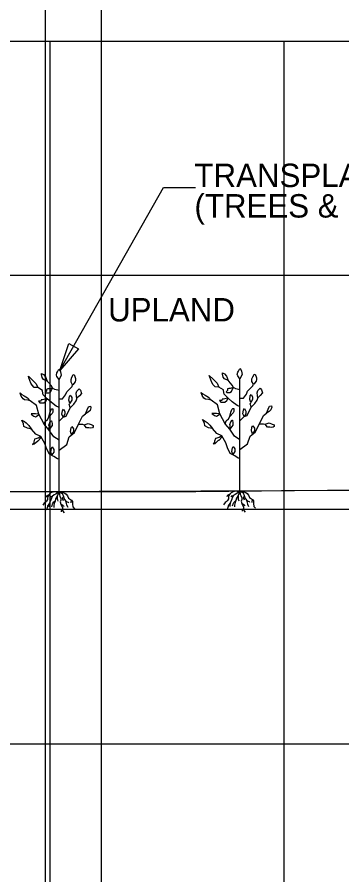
# Model space of a CAD drawing. Extents: x 1578769 to 1579225, y 724002 to 724828.
# Drawn here: x 1578839.43 to 1578846.37, y 724264.34 to 724282.66 of the extents above; entities that cross this region are included whole.
import ezdxf

# ---------------------------------------------------------------- set-up
doc = ezdxf.new("R2010")
doc.units = 0
for name, color, linetype in [('1', 7, 'Continuous'), ('Default', 7, 'Continuous'), ('Old_Level_1', 7, 'Continuous'), ('Old_Level_41', 7, 'Continuous'), ('R_Exist Surface', 7, 'Continuous')]:
    doc.layers.add(name, color=color, linetype=linetype)

msp = doc.modelspace()

# ---------------------------------------------------------------- linework, layer by layer
at = {"layer": '1'}
for p, q in [((1578840.327, 724272.523), (1578840.327, 724274.923)), ((1578844.196, 724272.536), (1578844.196, 724274.936)), ((1578840.332, 724272.518), (1578840.333, 724272.522)), ((1578844.201, 724272.531), (1578844.202, 724272.535))]:
    msp.add_line(p, q, dxfattribs=at)
for points in [[(1578840.345, 724275.111), (1578842.56, 724279.02), (1578843.246, 724279.02)], [(1578844.483, 724274.822), (1578844.452, 724274.879), (1578844.452, 724274.936), (1578844.47, 724274.98), (1578844.496, 724275.03), (1578844.521, 724275.037), (1578844.546, 724274.955), (1578844.546, 724274.917), (1578844.54, 724274.885), (1578844.489, 724274.822)], [(1578840.327, 724274.683), (1578840.239, 724274.708), (1578840.188, 724274.733), (1578840.163, 724274.784), (1578840.087, 724274.872), (1578840.075, 724274.885)], [(1578840.614, 724274.809), (1578840.583, 724274.866), (1578840.583, 724274.923), (1578840.602, 724274.967), (1578840.627, 724275.017), (1578840.652, 724275.024), (1578840.677, 724274.942), (1578840.677, 724274.904), (1578840.671, 724274.872), (1578840.62, 724274.809)], [(1578844.196, 724274.696), (1578844.108, 724274.721), (1578844.057, 724274.746), (1578844.032, 724274.797), (1578843.956, 724274.885), (1578843.944, 724274.898)], [(1578840.314, 724274.329), (1578840.264, 724274.354), (1578840.163, 724274.43), (1578840.075, 724274.506), (1578839.986, 724274.594), (1578839.974, 724274.67), (1578839.974, 724274.683), (1578839.873, 724274.746)], [(1578840.327, 724274.506), (1578840.403, 724274.506), (1578840.466, 724274.594), (1578840.491, 724274.657), (1578840.605, 724274.771), (1578840.617, 724274.809)], [(1578840.706, 724274.506), (1578840.693, 724274.626), (1578840.706, 724274.67), (1578840.756, 724274.721), (1578840.788, 724274.689), (1578840.807, 724274.62), (1578840.762, 724274.569), (1578840.706, 724274.519)], [(1578844.183, 724274.342), (1578844.133, 724274.367), (1578844.032, 724274.443), (1578843.944, 724274.519), (1578843.855, 724274.607), (1578843.843, 724274.683), (1578843.843, 724274.696), (1578843.742, 724274.759)], [(1578844.196, 724274.519), (1578844.272, 724274.519), (1578844.335, 724274.607), (1578844.36, 724274.67), (1578844.474, 724274.784), (1578844.486, 724274.822)], [(1578844.575, 724274.519), (1578844.562, 724274.639), (1578844.575, 724274.683), (1578844.625, 724274.733), (1578844.657, 724274.702), (1578844.676, 724274.632), (1578844.631, 724274.582), (1578844.575, 724274.531)], [(1578839.708, 724274.468), (1578839.664, 724274.481), (1578839.589, 724274.487), (1578839.557, 724274.506), (1578839.519, 724274.563), (1578839.494, 724274.626), (1578839.494, 724274.632), (1578839.532, 724274.601), (1578839.582, 724274.575), (1578839.652, 724274.531), (1578839.708, 724274.468)], [(1578840.327, 724274.038), (1578840.34, 724274.038), (1578840.415, 724274.114), (1578840.478, 724274.14), (1578840.567, 724274.316), (1578840.643, 724274.392), (1578840.693, 724274.468), (1578840.706, 724274.506)], [(1578840.561, 724274.417), (1578840.535, 724274.481), (1578840.548, 724274.556), (1578840.567, 724274.588), (1578840.598, 724274.537), (1578840.598, 724274.481), (1578840.561, 724274.417)], [(1578843.577, 724274.481), (1578843.533, 724274.493), (1578843.458, 724274.5), (1578843.426, 724274.519), (1578843.388, 724274.576), (1578843.363, 724274.639), (1578843.363, 724274.645), (1578843.401, 724274.613), (1578843.451, 724274.588), (1578843.521, 724274.544), (1578843.577, 724274.481)], [(1578844.196, 724273.635), (1578844.082, 724273.71), (1578843.981, 724273.862), (1578843.88, 724273.976), (1578843.767, 724274.19), (1578843.716, 724274.38), (1578843.577, 724274.481)], [(1578844.196, 724274.051), (1578844.209, 724274.051), (1578844.284, 724274.127), (1578844.347, 724274.152), (1578844.436, 724274.329), (1578844.512, 724274.405), (1578844.562, 724274.481), (1578844.575, 724274.519)], [(1578844.429, 724274.43), (1578844.404, 724274.493), (1578844.417, 724274.569), (1578844.436, 724274.601), (1578844.467, 724274.55), (1578844.467, 724274.493), (1578844.429, 724274.43)], [(1578840.327, 724273.622), (1578840.213, 724273.697), (1578840.112, 724273.849), (1578840.011, 724273.963), (1578839.898, 724274.177), (1578839.847, 724274.367), (1578839.708, 724274.468)], [(1578840.567, 724274.316), (1578840.561, 724274.354), (1578840.542, 724274.38), (1578840.561, 724274.417)], [(1578840.895, 724274.19), (1578840.927, 724274.272), (1578840.958, 724274.335), (1578841.002, 724274.348), (1578841.009, 724274.316), (1578840.99, 724274.26), (1578840.952, 724274.222), (1578840.895, 724274.19)], [(1578844.284, 724274.127), (1578844.259, 724274.19), (1578844.272, 724274.266), (1578844.291, 724274.298), (1578844.322, 724274.247), (1578844.322, 724274.19), (1578844.284, 724274.127)], [(1578844.436, 724274.329), (1578844.429, 724274.367), (1578844.411, 724274.392), (1578844.429, 724274.43)], [(1578844.764, 724274.203), (1578844.796, 724274.285), (1578844.827, 724274.348), (1578844.871, 724274.361), (1578844.878, 724274.329), (1578844.859, 724274.272), (1578844.821, 724274.235), (1578844.764, 724274.203)], [(1578839.898, 724274.177), (1578839.824, 724274.184), (1578839.766, 724274.184), (1578839.728, 724274.184), (1578839.747, 724274.164), (1578839.785, 724274.136), (1578839.824, 724274.126), (1578839.9, 724274.174)], [(1578840.011, 724273.963), (1578840.03, 724274.026), (1578840.081, 724274.064), (1578840.112, 724274.114)], [(1578840.327, 724273.414), (1578840.491, 724273.533), (1578840.542, 724273.697), (1578840.655, 724273.786), (1578840.744, 724273.963), (1578840.832, 724274.14), (1578840.895, 724274.19)], [(1578840.415, 724274.114), (1578840.39, 724274.177), (1578840.403, 724274.253), (1578840.422, 724274.285), (1578840.453, 724274.234), (1578840.453, 724274.177), (1578840.415, 724274.114)], [(1578843.767, 724274.19), (1578843.693, 724274.196), (1578843.635, 724274.196), (1578843.597, 724274.196), (1578843.616, 724274.177), (1578843.654, 724274.149), (1578843.693, 724274.139), (1578843.769, 724274.187)], [(1578843.88, 724273.976), (1578843.899, 724274.039), (1578843.95, 724274.077), (1578843.981, 724274.127)], [(1578844.196, 724273.427), (1578844.36, 724273.546), (1578844.411, 724273.71), (1578844.524, 724273.799), (1578844.612, 724273.976), (1578844.701, 724274.152), (1578844.764, 724274.203)], [(1578840.744, 724273.963), (1578840.807, 724273.963), (1578840.832, 724273.963), (1578840.863, 724273.95)], [(1578840.863, 724273.95), (1578840.952, 724273.982), (1578841.015, 724273.956), (1578841.059, 724273.937), (1578841.059, 724273.906), (1578841.04, 724273.887), (1578841.009, 724273.881), (1578840.964, 724273.887), (1578840.914, 724273.887), (1578840.863, 724273.95)], [(1578844.465, 724273.762), (1578844.44, 724273.825), (1578844.453, 724273.901), (1578844.472, 724273.932), (1578844.503, 724273.882), (1578844.503, 724273.825), (1578844.465, 724273.762)], [(1578844.612, 724273.976), (1578844.676, 724273.976), (1578844.701, 724273.976), (1578844.732, 724273.963)], [(1578844.732, 724273.963), (1578844.821, 724273.995), (1578844.884, 724273.969), (1578844.928, 724273.95), (1578844.928, 724273.919), (1578844.909, 724273.9), (1578844.878, 724273.893), (1578844.833, 724273.9), (1578844.783, 724273.9), (1578844.732, 724273.963)], [(1578840.33, 724273.219), (1578840.291, 724273.228), (1578840.215, 724273.276), (1578840.12, 724273.324), (1578840.062, 724273.448), (1578840.024, 724273.553), (1578839.938, 724273.706), (1578839.833, 724273.754), (1578839.738, 724273.859), (1578839.738, 724273.859)], [(1578840.596, 724273.749), (1578840.571, 724273.812), (1578840.584, 724273.888), (1578840.603, 724273.919), (1578840.634, 724273.869), (1578840.634, 724273.812), (1578840.596, 724273.749)], [(1578844.199, 724273.232), (1578844.16, 724273.241), (1578844.084, 724273.289), (1578843.989, 724273.337), (1578843.931, 724273.461), (1578843.893, 724273.566), (1578843.807, 724273.719), (1578843.702, 724273.767), (1578843.607, 724273.872), (1578843.607, 724273.872)], [(1578840.176, 724273.309), (1578840.151, 724273.372), (1578840.164, 724273.448), (1578840.183, 724273.48), (1578840.214, 724273.429), (1578840.214, 724273.372), (1578840.176, 724273.309)], [(1578844.045, 724273.322), (1578844.02, 724273.385), (1578844.033, 724273.461), (1578844.052, 724273.493), (1578844.083, 724273.442), (1578844.083, 724273.385), (1578844.045, 724273.322)], [(1578840.327, 724272.523), (1578840.276, 724272.517), (1578840.26, 724272.521), (1578840.202, 724272.513), (1578840.167, 724272.505), (1578840.14, 724272.49), (1578840.109, 724272.459), (1578840.085, 724272.424), (1578840.078, 724272.389), (1578840.078, 724272.358), (1578840.062, 724272.323), (1578840.051, 724272.307), (1578840.012, 724272.28), (1578839.977, 724272.234)], [(1578840.327, 724272.523), (1578840.26, 724272.474), (1578840.221, 724272.455), (1578840.182, 724272.424), (1578840.163, 724272.385), (1578840.155, 724272.354), (1578840.116, 724272.268), (1578840.082, 724272.226), (1578840.07, 724272.175), (1578840.054, 724272.133)], [(1578840.327, 724272.523), (1578840.287, 724272.428), (1578840.252, 724272.373), (1578840.241, 724272.323), (1578840.225, 724272.284), (1578840.214, 724272.226), (1578840.214, 724272.187)], [(1578840.327, 724272.523), (1578840.411, 724272.507), (1578840.454, 724272.494), (1578840.481, 724272.474), (1578840.508, 724272.435), (1578840.528, 724272.389), (1578840.594, 724272.342), (1578840.617, 724272.315), (1578840.617, 724272.257), (1578840.621, 724272.199), (1578840.66, 724272.16)], [(1578840.327, 724272.523), (1578840.396, 724272.486), (1578840.419, 724272.432), (1578840.431, 724272.377), (1578840.466, 724272.331), (1578840.489, 724272.245), (1578840.512, 724272.195)], [(1578840.327, 724272.523), (1578840.334, 724272.459), (1578840.345, 724272.432), (1578840.357, 724272.393), (1578840.365, 724272.377), (1578840.365, 724272.346), (1578840.353, 724272.307), (1578840.365, 724272.261), (1578840.38, 724272.226), (1578840.4, 724272.187), (1578840.4, 724272.152), (1578840.411, 724272.109), (1578840.435, 724272.074)], [(1578844.196, 724272.536), (1578844.145, 724272.53), (1578844.129, 724272.534), (1578844.071, 724272.526), (1578844.036, 724272.518), (1578844.009, 724272.503), (1578843.978, 724272.472), (1578843.954, 724272.437), (1578843.947, 724272.402), (1578843.947, 724272.371), (1578843.931, 724272.336), (1578843.92, 724272.32), (1578843.881, 724272.293), (1578843.846, 724272.246)], [(1578843.978, 724272.472), (1578843.935, 724272.452), (1578843.92, 724272.429), (1578843.908, 724272.421)], [(1578844.196, 724272.536), (1578844.129, 724272.487), (1578844.09, 724272.468), (1578844.051, 724272.437), (1578844.032, 724272.398), (1578844.024, 724272.367), (1578843.985, 724272.281), (1578843.951, 724272.239), (1578843.939, 724272.188), (1578843.923, 724272.145)], [(1578844.196, 724272.536), (1578844.156, 724272.441), (1578844.121, 724272.386), (1578844.11, 724272.336), (1578844.094, 724272.297), (1578844.082, 724272.239), (1578844.082, 724272.2)], [(1578844.196, 724272.536), (1578844.28, 724272.52), (1578844.323, 724272.507), (1578844.35, 724272.487), (1578844.377, 724272.448), (1578844.397, 724272.402), (1578844.463, 724272.355), (1578844.486, 724272.328), (1578844.486, 724272.27), (1578844.49, 724272.211), (1578844.529, 724272.173)], [(1578844.196, 724272.536), (1578844.265, 724272.499), (1578844.288, 724272.444), (1578844.3, 724272.39), (1578844.335, 724272.343), (1578844.358, 724272.258), (1578844.381, 724272.208)], [(1578844.196, 724272.536), (1578844.203, 724272.472), (1578844.214, 724272.444), (1578844.226, 724272.406), (1578844.234, 724272.39), (1578844.234, 724272.359), (1578844.222, 724272.32), (1578844.234, 724272.274), (1578844.249, 724272.239), (1578844.269, 724272.2), (1578844.269, 724272.165), (1578844.28, 724272.122), (1578844.304, 724272.087)], [(1578840.109, 724272.459), (1578840.066, 724272.439), (1578840.051, 724272.416), (1578840.039, 724272.408)], [(1578840.182, 724272.424), (1578840.14, 724272.416), (1578840.136, 724272.4)], [(1578840.241, 724272.323), (1578840.194, 724272.284), (1578840.19, 724272.265), (1578840.182, 724272.261), (1578840.163, 724272.202)], [(1578840.287, 724272.428), (1578840.287, 724272.373), (1578840.291, 724272.35), (1578840.303, 724272.319)], [(1578840.419, 724272.432), (1578840.407, 724272.4), (1578840.396, 724272.385), (1578840.415, 724272.338)], [(1578840.466, 724272.331), (1578840.501, 724272.311), (1578840.52, 724272.3), (1578840.532, 724272.288)], [(1578840.594, 724272.342), (1578840.582, 724272.303), (1578840.578, 724272.284)], [(1578843.985, 724272.281), (1578843.978, 724272.227), (1578843.982, 724272.211)], [(1578844.051, 724272.437), (1578844.009, 724272.429), (1578844.005, 724272.413)], [(1578844.11, 724272.336), (1578844.063, 724272.297), (1578844.059, 724272.277), (1578844.051, 724272.274), (1578844.032, 724272.215)], [(1578844.156, 724272.441), (1578844.156, 724272.386), (1578844.16, 724272.363), (1578844.172, 724272.332)], [(1578844.288, 724272.444), (1578844.276, 724272.413), (1578844.265, 724272.398), (1578844.284, 724272.351)], [(1578844.335, 724272.343), (1578844.37, 724272.324), (1578844.389, 724272.312), (1578844.401, 724272.301)], [(1578844.463, 724272.355), (1578844.451, 724272.316), (1578844.447, 724272.297)], [(1578840.116, 724272.268), (1578840.109, 724272.214), (1578840.113, 724272.199)], [(1578840.365, 724272.261), (1578840.4, 724272.245), (1578840.423, 724272.226), (1578840.427, 724272.21)], [(1578840.4, 724272.152), (1578840.373, 724272.117), (1578840.376, 724272.094)], [(1578844.234, 724272.274), (1578844.269, 724272.258), (1578844.292, 724272.239), (1578844.296, 724272.223)], [(1578844.269, 724272.165), (1578844.242, 724272.13), (1578844.245, 724272.107)]]:
    msp.add_lwpolyline(points, dxfattribs=at)
for points in [[(1578840.745, 724275.574), (1578840.345, 724275.111), (1578840.536, 724275.692)], [(1578840.075, 724274.885), (1578839.993, 724274.923), (1578839.967, 724274.961), (1578839.955, 724275.024), (1578839.955, 724275.049), (1578839.993, 724275.03), (1578840.037, 724274.98)], [(1578840.327, 724274.923), (1578840.283, 724274.986), (1578840.27, 724275.011), (1578840.283, 724275.062), (1578840.295, 724275.087), (1578840.321, 724275.144), (1578840.34, 724275.137), (1578840.359, 724275.087), (1578840.365, 724275.049), (1578840.371, 724275.011)], [(1578843.944, 724274.898), (1578843.862, 724274.936), (1578843.836, 724274.973), (1578843.824, 724275.037), (1578843.824, 724275.062), (1578843.862, 724275.043), (1578843.906, 724274.992)], [(1578844.196, 724274.936), (1578844.152, 724274.999), (1578844.139, 724275.024), (1578844.152, 724275.075), (1578844.164, 724275.1), (1578844.19, 724275.157), (1578844.209, 724275.15), (1578844.228, 724275.1), (1578844.234, 724275.062), (1578844.24, 724275.024)], [(1578839.873, 724274.746), (1578839.797, 724274.752), (1578839.753, 724274.796), (1578839.727, 724274.841), (1578839.683, 724274.954), (1578839.671, 724274.992), (1578839.746, 724274.923), (1578839.791, 724274.878), (1578839.841, 724274.828)], [(1578843.742, 724274.759), (1578843.666, 724274.765), (1578843.622, 724274.809), (1578843.596, 724274.853), (1578843.552, 724274.967), (1578843.54, 724275.005), (1578843.615, 724274.936), (1578843.66, 724274.891), (1578843.71, 724274.841)], [(1578840.188, 724274.733), (1578840.12, 724274.719), (1578840.091, 724274.719), (1578840.062, 724274.709), (1578840.062, 724274.671), (1578840.034, 724274.642), (1578840.053, 724274.633), (1578840.11, 724274.633), (1578840.148, 724274.652), (1578840.167, 724274.699)], [(1578844.057, 724274.746), (1578843.989, 724274.731), (1578843.96, 724274.731), (1578843.931, 724274.722), (1578843.931, 724274.684), (1578843.903, 724274.655), (1578843.922, 724274.645), (1578843.979, 724274.645), (1578844.017, 724274.665), (1578844.036, 724274.712)], [(1578840.075, 724274.506), (1578840.034, 724274.499), (1578839.976, 724274.489), (1578839.948, 724274.489), (1578839.938, 724274.461), (1578839.89, 724274.461), (1578839.919, 724274.422), (1578839.957, 724274.422), (1578840.005, 724274.422), (1578840.043, 724274.461)], [(1578843.944, 724274.519), (1578843.903, 724274.512), (1578843.845, 724274.502), (1578843.817, 724274.502), (1578843.807, 724274.474), (1578843.759, 724274.474), (1578843.788, 724274.435), (1578843.826, 724274.435), (1578843.874, 724274.435), (1578843.912, 724274.474)], [(1578843.981, 724274.127), (1578844, 724274.222), (1578844.013, 724274.26), (1578844.019, 724274.279), (1578844.044, 724274.304), (1578844.063, 724274.304), (1578844.063, 724274.235), (1578844.051, 724274.209)], [(1578840.112, 724274.114), (1578840.131, 724274.209), (1578840.144, 724274.247), (1578840.15, 724274.266), (1578840.176, 724274.291), (1578840.194, 724274.291), (1578840.194, 724274.222), (1578840.182, 724274.196)], [(1578839.738, 724273.859), (1578839.652, 724273.878), (1578839.575, 724273.916), (1578839.566, 724273.973), (1578839.528, 724274.05), (1578839.585, 724274.021), (1578839.623, 724273.993), (1578839.68, 724273.935), (1578839.709, 724273.897)], [(1578840.112, 724273.849), (1578840.12, 724273.926), (1578840.11, 724273.945), (1578840.129, 724274.002), (1578840.158, 724274.04), (1578840.167, 724274.04), (1578840.177, 724273.983), (1578840.177, 724273.935)], [(1578843.607, 724273.872), (1578843.521, 724273.891), (1578843.444, 724273.929), (1578843.435, 724273.986), (1578843.397, 724274.063), (1578843.454, 724274.034), (1578843.492, 724274.005), (1578843.549, 724273.948), (1578843.578, 724273.91)], [(1578843.981, 724273.862), (1578843.989, 724273.939), (1578843.979, 724273.958), (1578843.998, 724274.015), (1578844.027, 724274.053), (1578844.036, 724274.053), (1578844.046, 724273.996), (1578844.046, 724273.948)], [(1578839.938, 724273.706), (1578839.881, 724273.668), (1578839.805, 724273.649), (1578839.785, 724273.591), (1578839.785, 724273.553), (1578839.757, 724273.534), (1578839.795, 724273.544), (1578839.871, 724273.61), (1578839.881, 724273.61), (1578839.938, 724273.677)], [(1578843.807, 724273.719), (1578843.75, 724273.681), (1578843.674, 724273.661), (1578843.654, 724273.604), (1578843.654, 724273.566), (1578843.626, 724273.547), (1578843.664, 724273.556), (1578843.74, 724273.623), (1578843.75, 724273.623), (1578843.807, 724273.69)]]:
    msp.add_lwpolyline(points, close=True, dxfattribs=at)
at = {"layer": 'Default'}
for p, q in [((1578841.23, 724437.474), (1578841.23, 724187.474)), ((1578840.032, 724387.146), (1578840.032, 724137.146))]:
    msp.add_line(p, q, dxfattribs=at)
msp.add_lwpolyline([(1578826.025, 724272.503), (1578843.356, 724272.54), (1578848.216, 724272.563), (1578852.656, 724272.595), (1578873.806, 724272.679), (1578875.706, 724271.556), (1578889.515, 724263.067), (1578894.196, 724261.454), (1578913.456, 724256.023), (1578914.486, 724256.05), (1578915.035, 724256.065), (1578992.496, 724256.633), (1578992.515, 724256.633), (1578992.566, 724256.634), (1578992.736, 724256.639), (1578993.706, 724256.668), (1579090.356, 724259.528), (1579113.086, 724262.229), (1579131.176, 724264.398), (1579155.015, 724266.722), (1579177.006, 724269.229), (1579191.525, 724270.885)], dxfattribs=at)
at = {"layer": 'Old_Level_1'}
msp.add_lwpolyline([(1578825.135, 724282.141), (1578925.135, 724282.141), (1578925.135, 724252.141), (1578825.135, 724252.141)], close=True, dxfattribs=at)
at = {"layer": 'Old_Level_41'}
for p, q in [((1578840.135, 724252.141), (1578840.135, 724282.141)), ((1578845.135, 724282.141), (1578845.135, 724252.141))]:
    msp.add_line(p, q, dxfattribs=at)
for points in [[(1578925.135, 724277.141), (1578825.135, 724277.141)], [(1578925.135, 724272.141), (1578825.135, 724272.141)], [(1578825.135, 724267.141), (1578925.135, 724267.141)]]:
    msp.add_lwpolyline(points, dxfattribs=at)
at = {"layer": 'R_Exist Surface'}
msp.add_lwpolyline([(1578826.062, 724272.509), (1578843.255, 724272.529), (1578855.204, 724272.649), (1578859.177, 724272.597), (1578872.167, 724272.617), (1578873.087, 724272.657), (1578874.163, 724272.457), (1578875.161, 724271.898), (1578886.138, 724265.225), (1578890.363, 724262.7), (1578891.18, 724262.468), (1578894.233, 724261.427), (1578900.147, 724259.744), (1578907.197, 724257.773), (1578912.15, 724256.411), (1578913.135, 724256.113), (1578914.178, 724256.033), (1578918.136, 724256.056), (1578925.136, 724256.105)], dxfattribs=at)

# ---------------------------------------------------------------- texts
at = {"layer": '1'}
for s, p in [('TRANSPLANT OR BARE ROOT SEEDLINGS ', (1578843.222, 724279.029)), ('(TREES & BUSHES)', (1578843.222, 724278.378)), ('UPLAND', (1578841.376, 724276.16))]:
    msp.add_text(s, height=0.5, dxfattribs=at).set_placement(p)

doc.saveas('drawing.dxf')
